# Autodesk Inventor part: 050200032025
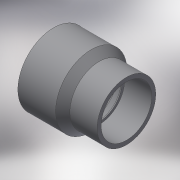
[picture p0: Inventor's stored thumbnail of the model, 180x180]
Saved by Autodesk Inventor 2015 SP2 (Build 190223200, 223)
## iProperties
Created: 2017-10
Part Number: 050200032025
Material: Generic
Description: PLASSON REDUCING SOCKET M.F.32(25)25 CEMENTED
Document SubType Name: Modeling
Designer: KIM
Density: 1 g/cm^3
Appearance: Default
Author: KIM
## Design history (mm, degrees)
derived "050200.ipt"
feature "Solid1::050200.ipt"
tag "TaggingFeature1"
body "Solid1"
other parameters: "d1" = 22, "d2" = 19, "d3" = 19, "d4" = 25, "d5" = 31, "d6" = 25, "d7" = 32, "d8" = 22.5, "d9" = 45 deg, "d12" = 0.25, "d_" = 25, "d_1" = 25, "L_" = 22, "l_" = 19, "l_1" = 19, "E_" = 31, "D_" = 32, "d11" = 0.55499
